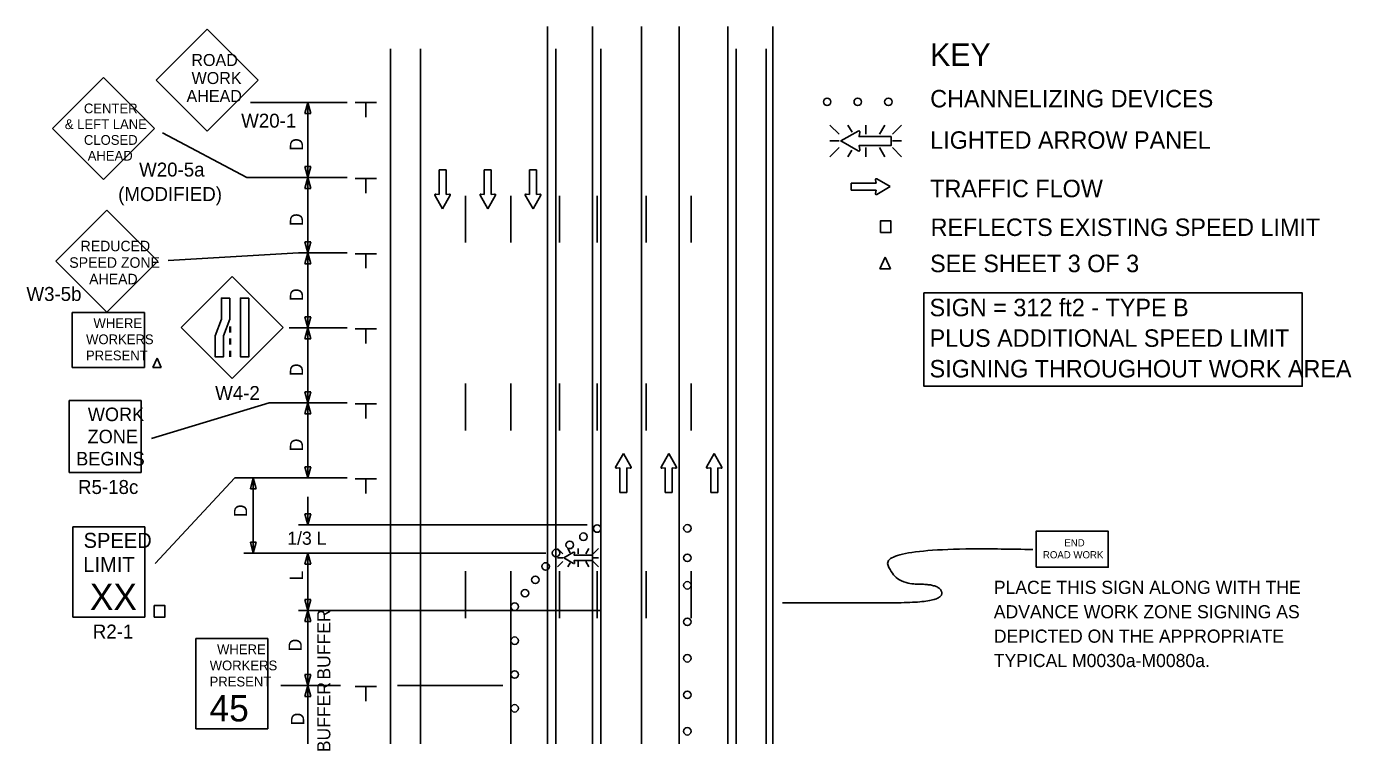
# Model space of a CAD drawing. Extents: x 16724 to 19504, y 5662 to 6979.
# Drawn here: x 16724 to 17429, y 6551 to 6929 of the extents above; entities that cross this region are included whole.
import ezdxf

# ---------------------------------------------------------------- set-up
doc = ezdxf.new("R2010")
doc.units = 0
for name, color, linetype in [('ALI_LEGAL_EX', 7, 'Continuous'), ('MT_SCRATCH_LEVEL_E', 7, 'Continuous'), ('PAVT_EDGE_EX', 7, 'Continuous'), ('TRAFFIC_SIGNS_PR', 7, 'Continuous'), ('TYPICAL_TEXT_DIMEN_EX', 7, 'Continuous'), ('TYPICAL_TEXT_DIMEN_PR', 7, 'Continuous')]:
    doc.layers.add(name, color=color, linetype=linetype)

msp = doc.modelspace()

# ---------------------------------------------------------------- linework, layer by layer
at = {"layer": 'ALI_LEGAL_EX'}
for p, q in [((17001.36, 6131.68), (17001.36, 6928.96)), ((17001.36, 6131.68), (17001.36, 6928.96)), ((17025.36, 6131.68), (17025.36, 6928.96)), ((17025.36, 6131.68), (17025.36, 6928.96)), ((17051.36, 6131.68), (17051.36, 6928.96)), ((17051.36, 6131.68), (17051.36, 6928.96)), ((17071.36, 6131.68), (17071.36, 6928.96)), ((17071.36, 6131.68), (17071.36, 6928.96)), ((17097.36, 6131.68), (17097.36, 6928.96)), ((17097.36, 6131.68), (17097.36, 6928.96)), ((17121.36, 6131.68), (17121.36, 6928.96)), ((17121.36, 6131.68), (17121.36, 6928.96))]:
    msp.add_line(p, q, dxfattribs=at)
for points in [[(16957.81, 6813.81), (16957.81, 6838.81)], [(16981.81, 6813.81), (16981.81, 6838.81)], [(17007.81, 6813.81), (17007.81, 6838.81)], [(17027.81, 6813.81), (17027.81, 6838.81)], [(17053.81, 6813.81), (17053.81, 6838.81)], [(17077.81, 6813.81), (17077.81, 6838.81)], [(16957.81, 6713.81), (16957.81, 6738.81)], [(16981.81, 6713.81), (16981.81, 6738.81)], [(17007.81, 6713.81), (17007.81, 6738.81)], [(17027.81, 6713.81), (17027.81, 6738.81)], [(17053.81, 6713.81), (17053.81, 6738.81)], [(17077.81, 6713.81), (17077.81, 6738.81)], [(16957.81, 6613.81), (16957.81, 6638.81)], [(16981.81, 6613.81), (16981.81, 6638.81)], [(17007.81, 6613.81), (17007.81, 6638.81)], [(17027.81, 6613.81), (17027.81, 6638.81)], [(17053.81, 6613.81), (17053.81, 6638.81)], [(17077.81, 6613.81), (17077.81, 6638.81)]]:
    msp.add_lwpolyline(points, dxfattribs=at)
at = {"layer": 'MT_SCRATCH_LEVEL_E'}
for p, q in [((16947.41, 6852.65), (16943.67, 6852.65)), ((16943.67, 6852.65), (16943.67, 6839.4)), ((16947.41, 6852.65), (16943.67, 6852.65)), ((16943.67, 6852.65), (16943.67, 6839.4)), ((16947.41, 6839.4), (16947.41, 6852.65)), ((16947.41, 6839.4), (16947.41, 6852.65)), ((16971.48, 6852.65), (16967.74, 6852.65)), ((16967.74, 6852.65), (16967.74, 6839.4)), ((16971.48, 6852.65), (16967.74, 6852.65)), ((16967.74, 6852.65), (16967.74, 6839.4)), ((16971.48, 6839.4), (16971.48, 6852.65)), ((16971.48, 6839.4), (16971.48, 6852.65)), ((16995.55, 6852.65), (16991.81, 6852.65)), ((16991.81, 6852.65), (16991.81, 6839.4)), ((16995.55, 6852.65), (16991.81, 6852.65)), ((16991.81, 6852.65), (16991.81, 6839.4)), ((16995.55, 6839.4), (16995.55, 6852.65)), ((16995.55, 6839.4), (16995.55, 6852.65)), ((17175.9, 6847.27), (17176.21, 6845.5)), ((17175.9, 6847.27), (17176.21, 6845.5)), ((17183.82, 6843.64), (17176.58, 6847.75)), ((17183.82, 6843.64), (17176.58, 6847.75)), ((16943.67, 6839.4), (16941.89, 6839.71)), ((16943.67, 6839.4), (16941.89, 6839.71)), ((16949.19, 6839.71), (16947.41, 6839.4)), ((16949.19, 6839.71), (16947.41, 6839.4)), ((16967.74, 6839.4), (16965.96, 6839.71)), ((16967.74, 6839.4), (16965.96, 6839.71)), ((16973.26, 6839.71), (16971.48, 6839.4)), ((16973.26, 6839.71), (16971.48, 6839.4)), ((16991.81, 6839.4), (16990.03, 6839.71)), ((16991.81, 6839.4), (16990.03, 6839.71)), ((16997.33, 6839.71), (16995.55, 6839.4)), ((16997.33, 6839.71), (16995.55, 6839.4)), ((17176.21, 6845.5), (17162.96, 6845.5)), ((17162.96, 6845.5), (17162.96, 6841.75)), ((17176.21, 6845.5), (17162.96, 6845.5)), ((17162.96, 6845.5), (17162.96, 6841.75)), ((17162.96, 6841.75), (17176.21, 6841.75)), ((17162.96, 6841.75), (17176.21, 6841.75)), ((17176.21, 6841.75), (17175.9, 6839.98)), ((17176.21, 6841.75), (17175.9, 6839.98)), ((17176.58, 6839.5), (17183.82, 6843.64)), ((17176.58, 6839.5), (17183.82, 6843.64)), ((16941.41, 6839.03), (16945.56, 6831.79)), ((16941.41, 6839.03), (16945.56, 6831.79)), ((16945.56, 6831.79), (16949.67, 6839.03)), ((16945.56, 6831.79), (16949.67, 6839.03)), ((16965.48, 6839.03), (16969.63, 6831.79)), ((16965.48, 6839.03), (16969.63, 6831.79)), ((16969.63, 6831.79), (16973.74, 6839.03)), ((16969.63, 6831.79), (16973.74, 6839.03)), ((16989.55, 6839.03), (16993.7, 6831.79)), ((16989.55, 6839.03), (16993.7, 6831.79)), ((16993.7, 6831.79), (16997.81, 6839.03)), ((16993.7, 6831.79), (16997.81, 6839.03)), ((17041.75, 6701.53), (17037.64, 6694.29)), ((17041.75, 6701.53), (17037.64, 6694.29)), ((17045.89, 6694.29), (17041.75, 6701.53)), ((17045.89, 6694.29), (17041.75, 6701.53)), ((17065.92, 6701.53), (17061.81, 6694.29)), ((17065.92, 6701.53), (17061.81, 6694.29)), ((17070.06, 6694.29), (17065.92, 6701.53)), ((17070.06, 6694.29), (17065.92, 6701.53)), ((17090.09, 6701.53), (17085.97, 6694.29)), ((17090.09, 6701.53), (17085.97, 6694.29)), ((17094.23, 6694.29), (17090.09, 6701.53)), ((17094.23, 6694.29), (17090.09, 6701.53)), ((17038.12, 6693.61), (17039.89, 6693.92)), ((17038.12, 6693.61), (17039.89, 6693.92)), ((17039.89, 6693.92), (17039.89, 6680.67)), ((17039.89, 6693.92), (17039.89, 6680.67)), ((17043.64, 6680.67), (17043.64, 6693.92)), ((17043.64, 6693.92), (17045.41, 6693.61)), ((17043.64, 6680.67), (17043.64, 6693.92)), ((17043.64, 6693.92), (17045.41, 6693.61)), ((17062.29, 6693.61), (17064.06, 6693.92)), ((17062.29, 6693.61), (17064.06, 6693.92)), ((17064.06, 6693.92), (17064.06, 6680.67)), ((17064.06, 6693.92), (17064.06, 6680.67)), ((17067.81, 6680.67), (17067.81, 6693.92)), ((17067.81, 6693.92), (17069.58, 6693.61)), ((17067.81, 6680.67), (17067.81, 6693.92)), ((17067.81, 6693.92), (17069.58, 6693.61)), ((17086.46, 6693.61), (17088.23, 6693.92)), ((17086.46, 6693.61), (17088.23, 6693.92)), ((17088.23, 6693.92), (17088.23, 6680.67)), ((17088.23, 6693.92), (17088.23, 6680.67)), ((17091.98, 6680.67), (17091.98, 6693.92)), ((17091.98, 6693.92), (17093.75, 6693.61)), ((17091.98, 6680.67), (17091.98, 6693.92)), ((17091.98, 6693.92), (17093.75, 6693.61)), ((17039.89, 6680.67), (17043.64, 6680.67)), ((17039.89, 6680.67), (17043.64, 6680.67)), ((17064.06, 6680.67), (17067.81, 6680.67)), ((17064.06, 6680.67), (17067.81, 6680.67)), ((17088.23, 6680.67), (17091.98, 6680.67)), ((17088.23, 6680.67), (17091.98, 6680.67))]:
    msp.add_line(p, q, dxfattribs=at)
for centre, start, end in [((17176.36, 6847.35), 60.42484, 189.96381), ((17176.36, 6847.35), 60.42484, 189.96381), ((16941.82, 6839.25), 80.03619, 209.77312), ((16941.82, 6839.25), 80.03619, 209.77312), ((16949.26, 6839.25), 330.42484, 99.96381), ((16949.26, 6839.25), 330.42484, 99.96381), ((16965.89, 6839.25), 80.03619, 209.77312), ((16965.89, 6839.25), 80.03619, 209.77312), ((16973.33, 6839.25), 330.42484, 99.96381), ((16973.33, 6839.25), 330.42484, 99.96381), ((16989.96, 6839.25), 80.03619, 209.77312), ((16989.96, 6839.25), 80.03619, 209.77312), ((16997.4, 6839.25), 330.42484, 99.96381), ((16997.4, 6839.25), 330.42484, 99.96381), ((17176.36, 6839.91), 170.03619, 299.77312), ((17176.36, 6839.91), 170.03619, 299.77312), ((17038.04, 6694.07), 150.42484, 279.96381), ((17038.04, 6694.07), 150.42484, 279.96381), ((17045.48, 6694.07), 260.03619, 29.77312), ((17045.48, 6694.07), 260.03619, 29.77312), ((17062.21, 6694.07), 150.42484, 279.96381), ((17062.21, 6694.07), 150.42484, 279.96381), ((17069.65, 6694.07), 260.03619, 29.77312), ((17069.65, 6694.07), 260.03619, 29.77312), ((17086.38, 6694.07), 150.42484, 279.96381), ((17086.38, 6694.07), 150.42484, 279.96381), ((17093.82, 6694.07), 260.03619, 29.77312), ((17093.82, 6694.07), 260.03619, 29.77312)]:
    msp.add_arc(centre, 0.463, start, end, dxfattribs=at)
at = {"layer": 'PAVT_EDGE_EX'}
for p, q in [((16917.81, 6917), (16917.81, 6089.02)), ((16933.81, 6917), (16933.81, 6089.02)), ((17005.81, 6917), (17005.81, 6089.02)), ((17029.81, 6917), (17029.81, 6089.02)), ((17101.81, 6917), (17101.81, 6089.02)), ((17117.81, 6917), (17117.81, 6089.02))]:
    msp.add_line(p, q, dxfattribs=at)
msp.add_lwpolyline([(17029.81, 6617.94), (16981.81, 6617.94), (16981.81, 6537.94), (17029.81, 6537.94)], close=True, dxfattribs=at)
at = {"layer": 'TRAFFIC_SIGNS_PR'}
for p, q in [((16820.31, 6927.52), (16793.16, 6900.36)), ((16847.46, 6900.36), (16820.31, 6927.52)), ((16765.09, 6901.75), (16737.93, 6874.6)), ((16792.24, 6874.6), (16765.09, 6901.75)), ((16793.16, 6900.36), (16820.31, 6873.21)), ((16820.31, 6873.21), (16847.46, 6900.36)), ((17151.69, 6876.45), (17156.62, 6871.52)), ((17163.45, 6872.63), (17161.24, 6876.45)), ((17170.77, 6871.52), (17170.77, 6876.45)), ((17178, 6871.52), (17180.85, 6876.45)), ((17184.92, 6871.52), (17189.85, 6876.45)), ((16737.93, 6874.6), (16765.09, 6847.45)), ((16765.09, 6847.45), (16792.24, 6874.6)), ((17156.62, 6867.96), (17151.69, 6867.96)), ((17184.92, 6867.96), (17189.85, 6867.96)), ((17151.69, 6859.47), (17156.62, 6864.41)), ((17161.2, 6859.47), (17163.31, 6863.13)), ((17170.77, 6864.41), (17170.77, 6859.47)), ((17180.9, 6859.47), (17178.05, 6864.41)), ((17184.92, 6864.41), (17189.85, 6859.47)), ((16766.85, 6831.07), (16739.69, 6803.91)), ((16794, 6803.91), (16766.85, 6831.07)), ((16739.69, 6803.91), (16766.85, 6776.76)), ((16766.85, 6776.76), (16794, 6803.91)), ((16833.56, 6795.73), (16806.4, 6768.58)), ((16860.71, 6768.58), (16833.56, 6795.73)), ((16748.45, 6776.64), (16786.85, 6776.64)), ((16748.45, 6747.32), (16748.45, 6776.64)), ((16786.85, 6747.32), (16786.85, 6776.64)), ((16806.4, 6768.58), (16833.56, 6741.43)), ((16832.31, 6769.07), (16832.31, 6765.87)), ((16832.31, 6762.67), (16832.31, 6759.47)), ((16832.71, 6769.07), (16832.71, 6765.87)), ((16832.71, 6762.67), (16832.71, 6759.47)), ((16833.56, 6741.43), (16860.71, 6768.58)), ((16832.31, 6756.27), (16832.31, 6753.07)), ((16832.71, 6756.27), (16832.71, 6753.07)), ((16748.45, 6747.32), (16786.85, 6747.32)), ((16746.75, 6691.37), (16746.75, 6729.77)), ((16746.75, 6729.77), (16785.15, 6729.77)), ((16785.15, 6691.37), (16785.15, 6729.77)), ((16746.75, 6691.37), (16785.15, 6691.37)), ((16748.74, 6662.36), (16787.14, 6662.36)), ((16748.74, 6614.36), (16748.74, 6662.36)), ((16787.14, 6614.36), (16787.14, 6662.36)), ((17006.73, 6650.82), (17009.55, 6648)), ((17013.45, 6648.63), (17012.19, 6650.82)), ((17017.63, 6648), (17017.63, 6650.82)), ((17021.76, 6648), (17023.39, 6650.82)), ((17025.72, 6648), (17028.54, 6650.82)), ((17009.55, 6645.97), (17006.73, 6645.97)), ((17006.73, 6641.12), (17009.55, 6643.94)), ((17012.16, 6641.11), (17013.37, 6643.21)), ((17017.63, 6643.94), (17017.63, 6641.11)), ((17023.42, 6641.11), (17021.79, 6643.94)), ((17025.72, 6645.97), (17028.54, 6645.97)), ((17025.72, 6643.94), (17028.54, 6641.11)), ((16748.74, 6614.36), (16787.14, 6614.36)), ((16814.23, 6602.91), (16852.63, 6602.91)), ((16814.23, 6554.91), (16814.23, 6602.91)), ((16852.63, 6554.91), (16852.63, 6602.91)), ((16814.23, 6554.91), (16852.63, 6554.91))]:
    msp.add_line(p, q, dxfattribs=at)
for points in [[(17166.7, 6873.24), (17157.41, 6867.96), (17166.7, 6862.64)], [(17167.57, 6863.27), (17167.17, 6865.54), (17184.18, 6865.54), (17184.18, 6870.34), (17167.17, 6870.34), (17167.57, 6872.62)], [(17181.07, 6806.1), (17178.28, 6799.93)], [(17178.28, 6799.93), (17181.07, 6806.1)], [(17183.87, 6799.93), (17181.07, 6806.1)], [(17181.07, 6806.1), (17183.87, 6799.93)], [(17178.28, 6799.93), (17183.87, 6799.93)], [(17183.87, 6799.93), (17178.28, 6799.93)], [(16793.6, 6752.26), (16791.37, 6747.32)], [(16791.37, 6747.32), (16793.6, 6752.26)], [(16795.84, 6747.32), (16793.6, 6752.26)], [(16793.6, 6752.26), (16795.84, 6747.32)], [(16791.37, 6747.32), (16795.84, 6747.32)], [(16795.84, 6747.32), (16791.37, 6747.32)], [(17015.3, 6648.98), (17009.99, 6645.97), (17015.3, 6642.93)], [(17015.8, 6643.28), (17015.57, 6644.58), (17025.3, 6644.58), (17025.3, 6647.32), (17015.57, 6647.32), (17015.81, 6648.63)]]:
    msp.add_lwpolyline(points, dxfattribs=at)
for points in [[(17178.57, 6819.2), (17184.16, 6819.2), (17184.16, 6825.37), (17178.57, 6825.37)], [(16832.31, 6784.31), (16832.31, 6773.13), (16828.97, 6764.25), (16828.97, 6753.07), (16824.47, 6753.07), (16824.47, 6764.25), (16827.82, 6773.13), (16827.82, 6784.31)], [(16842.45, 6784.31), (16842.45, 6753.07), (16837.95, 6753.07), (16837.95, 6784.31)], [(17261.42, 6640.9), (17299.82, 6640.9), (17299.82, 6660.1), (17261.42, 6660.1)], [(16792.15, 6614.36), (16797.75, 6614.36), (16797.75, 6620.53), (16792.15, 6620.53)]]:
    msp.add_lwpolyline(points, close=True, dxfattribs=at)
for centre in [(17150.2, 6888.8), (17166.5, 6888.8), (17182.8, 6888.8), (17027.8, 6661.52), (17075.83, 6661.64), (17020.5, 6657.17), (17005.9, 6648.47), (17013.2, 6652.82), (17000.4, 6641.34), (17075.79, 6645.93), (16994.9, 6634.21), (16989.41, 6627.09), (17075.79, 6631.28), (16983.91, 6619.95), (17075.79, 6611.84), (16983.91, 6601.76), (17075.79, 6592.4), (16983.91, 6583.76), (17075.79, 6572.96), (16983.91, 6565.76), (17075.79, 6553.52)]:
    msp.add_circle(centre, 2, dxfattribs=at)
for centre, radius, start, end in [((17166.98, 6872.71), 0.598, 350.73078, 118.89165), ((17166.98, 6863.17), 0.597, 241.48329, 9.95933), ((17015.47, 6648.68), 0.341, 350.73078, 118.89165), ((17015.47, 6643.23), 0.341, 241.48329, 9.95933)]:
    msp.add_arc(centre, radius, start, end, dxfattribs=at)
at = {"layer": 'TYPICAL_TEXT_DIMEN_EX'}
msp.add_lwpolyline([(17201.7, 6787.03), (17403.05, 6787.03), (17403.05, 6737.36), (17201.7, 6737.36)], close=True, dxfattribs=at)
at = {"layer": 'TYPICAL_TEXT_DIMEN_PR'}
for p, q in [((16843.26, 6888.47), (16894.81, 6888.47)), ((16872.24, 6882.6), (16873.81, 6888.47)), ((16873.81, 6882.6), (16872.24, 6882.6)), ((16873.81, 6888.47), (16875.38, 6882.6)), ((16873.81, 6888.47), (16873.81, 6848.47)), ((16875.38, 6882.6), (16873.81, 6882.6)), ((16899.06, 6888.47), (16910.31, 6888.47)), ((16904.69, 6888.47), (16904.69, 6880.68)), ((16796.57, 6872.3), (16841.3, 6848.47)), ((16873.81, 6848.47), (16872.24, 6854.33)), ((16872.24, 6854.33), (16873.81, 6854.33)), ((16873.81, 6854.33), (16875.38, 6854.33)), ((16875.38, 6854.33), (16873.81, 6848.47)), ((16841.3, 6848.47), (16894.81, 6848.47)), ((16872.24, 6842.6), (16873.81, 6848.47)), ((16873.81, 6848.47), (16875.38, 6842.6)), ((16873.81, 6848.47), (16873.81, 6808.47)), ((16899.06, 6847.94), (16910.31, 6847.94)), ((16904.69, 6847.94), (16904.69, 6840.15)), ((16873.81, 6842.6), (16872.24, 6842.6)), ((16875.38, 6842.6), (16873.81, 6842.6)), ((16873.81, 6808.47), (16872.24, 6814.33)), ((16872.24, 6814.33), (16873.81, 6814.33)), ((16873.81, 6814.33), (16875.38, 6814.33)), ((16875.38, 6814.33), (16873.81, 6808.47)), ((16868.81, 6808.47), (16799.51, 6804.25)), ((16868.81, 6808.47), (16894.81, 6808.47)), ((16872.24, 6802.6), (16873.81, 6808.47)), ((16873.81, 6808.47), (16875.38, 6802.6)), ((16873.81, 6808.47), (16873.81, 6768.47)), ((16899.06, 6807.94), (16910.31, 6807.94)), ((16904.69, 6807.94), (16904.69, 6800.15)), ((16873.81, 6802.6), (16872.24, 6802.6)), ((16875.38, 6802.6), (16873.81, 6802.6)), ((16873.81, 6768.47), (16872.24, 6774.33)), ((16872.24, 6774.33), (16873.81, 6774.33)), ((16873.81, 6774.33), (16875.38, 6774.33)), ((16875.38, 6774.33), (16873.81, 6768.47)), ((16863.88, 6768.47), (16894.81, 6768.47)), ((16872.24, 6762.6), (16873.81, 6768.47)), ((16873.81, 6762.6), (16872.24, 6762.6)), ((16873.81, 6768.47), (16875.38, 6762.6)), ((16873.81, 6768.47), (16873.81, 6728.47)), ((16875.38, 6762.6), (16873.81, 6762.6)), ((16899.06, 6767.94), (16910.31, 6767.94)), ((16904.69, 6767.94), (16904.69, 6760.15)), ((16873.81, 6728.47), (16872.24, 6734.33)), ((16872.24, 6734.33), (16873.81, 6734.33)), ((16873.81, 6734.33), (16875.38, 6734.33)), ((16875.38, 6734.33), (16873.81, 6728.47)), ((16853.18, 6728.47), (16790.66, 6709.54)), ((16853.18, 6728.47), (16894.81, 6728.47)), ((16872.24, 6722.6), (16873.81, 6728.47)), ((16873.81, 6728.47), (16875.38, 6722.6)), ((16873.81, 6728.47), (16873.81, 6688.47)), ((16899.06, 6727.94), (16910.31, 6727.94)), ((16904.69, 6727.94), (16904.69, 6720.15)), ((16873.81, 6722.6), (16872.24, 6722.6)), ((16875.38, 6722.6), (16873.81, 6722.6)), ((16873.81, 6688.47), (16872.24, 6694.33)), ((16872.24, 6694.33), (16873.81, 6694.33)), ((16873.81, 6694.33), (16875.38, 6694.33)), ((16875.38, 6694.33), (16873.81, 6688.47)), ((16834.91, 6688.47), (16792.53, 6642.95)), ((16834.91, 6688.47), (16873.81, 6688.47)), ((16843.25, 6682.6), (16844.82, 6688.47)), ((16844.82, 6688.47), (16844.82, 6648.47)), ((16844.82, 6688.47), (16846.39, 6682.6)), ((16868.81, 6688.47), (16894.81, 6688.47)), ((16899.06, 6687.94), (16910.31, 6687.94)), ((16904.69, 6687.94), (16904.69, 6680.15)), ((16844.82, 6682.6), (16843.25, 6682.6)), ((16846.39, 6682.6), (16844.82, 6682.6)), ((16873.81, 6663.53), (16873.81, 6678.46)), ((16868.81, 6663.53), (17022.42, 6663.53)), ((16873.81, 6663.53), (16872.24, 6669.4)), ((16872.24, 6669.4), (16873.81, 6669.4)), ((16873.81, 6669.4), (16875.38, 6669.4)), ((16875.38, 6669.4), (16873.81, 6663.53)), ((16844.82, 6648.47), (16843.25, 6654.33)), ((16843.25, 6654.33), (16844.82, 6654.33)), ((16844.82, 6654.33), (16846.39, 6654.33)), ((16846.39, 6654.33), (16844.82, 6648.47)), ((16839.82, 6648.47), (17000.57, 6648.47)), ((16872.24, 6642.6), (16873.81, 6648.47)), ((16873.81, 6642.6), (16872.24, 6642.6)), ((16873.81, 6648.47), (16875.38, 6642.6)), ((16873.81, 6648.47), (16873.81, 6617.94)), ((16875.38, 6642.6), (16873.81, 6642.6)), ((16873.81, 6617.94), (16872.24, 6623.8)), ((16872.24, 6623.8), (16873.81, 6623.8)), ((16873.81, 6623.8), (16875.38, 6623.8)), ((16875.38, 6623.8), (16873.81, 6617.94)), ((16868.81, 6617.94), (17029.81, 6617.94)), ((16872.24, 6612.08), (16873.81, 6617.94)), ((16873.81, 6617.94), (16873.81, 6577.94)), ((16873.81, 6617.94), (16875.38, 6612.08)), ((16873.81, 6612.08), (16872.24, 6612.08)), ((16875.38, 6612.08), (16873.81, 6612.08)), ((16873.81, 6577.94), (16872.24, 6583.8)), ((16872.24, 6583.8), (16873.81, 6583.8)), ((16873.81, 6583.8), (16875.38, 6583.8)), ((16875.38, 6583.8), (16873.81, 6577.94)), ((16859.39, 6577.94), (16891.23, 6577.94)), ((16872.24, 6572.08), (16873.81, 6577.94)), ((16873.81, 6572.08), (16872.24, 6572.08)), ((16873.81, 6577.94), (16873.81, 6537.94)), ((16873.81, 6577.94), (16875.38, 6572.08)), ((16875.38, 6572.08), (16873.81, 6572.08)), ((16899.06, 6577.41), (16910.31, 6577.41)), ((16904.69, 6577.41), (16904.69, 6569.63)), ((16921.53, 6577.94), (16977.55, 6577.94))]:
    msp.add_line(p, q, dxfattribs=at)
msp.add_open_spline([(17259.69, 6650.35), (17179.04, 6652.51), (17186.04, 6631.92), (17211.21, 6631.92), (17211.21, 6622.01), (17161.57, 6622.01), (17126.5, 6622.01)], degree=2, dxfattribs=at)

# ---------------------------------------------------------------- texts
at = {"layer": 'TRAFFIC_SIGNS_PR'}
for s, height, p in [('ROAD', 6.4, (16811.85, 6907.9)), ('WORK', 6.4, (16811.96, 6898.3)), ('AHEAD', 6.4, (16809.27, 6888.7)), ('CENTER', 5.2, (16754.66, 6882.71)), ('W20-1', 7.44, (16838.37, 6875.06)), ('& LEFT LANE', 5.2, (16744.53, 6874.31)), ('CLOSED', 5.2, (16754.67, 6865.91)), ('AHEAD', 5.2, (16756.69, 6857.51)), ('W20-5a', 7.44, (16784.04, 6849.02)), ('(MODIFIED)', 7.44, (16772.9, 6835.98)), ('REDUCED', 5.6, (16752.9, 6809.22)), ('SPEED ZONE', 5.6, (16746.9, 6800.42)), ('W3-5b', 7.44, (16724.08, 6782.76)), ('AHEAD', 5.6, (16757.46, 6791.62)), ('WHERE', 5.2, (16759.76, 6768.32)), ('WORKERS', 5.2, (16755.84, 6759.72)), ('PRESENT', 5.2, (16755.77, 6751.12)), ('W4-2', 7.44, (16824.51, 6729.99)), ('WORK', 7.217, (16756.75, 6718.74)), ('ZONE', 7.217, (16756.63, 6706.93)), ('BEGINS', 7.217, (16750.56, 6695.12)), ('R5-18c', 7.44, (16751.56, 6679.93)), ('SPEED', 8, (16754.5, 6651.23)), ('ROAD WORK', 3.831, (17265.03, 6645.65)), ('END', 3.831, (17276.43, 6652.03)), ('LIMIT', 8, (16754.34, 6638.43)), ('XX', 14.031, (16757.85, 6618.12)), ('PLACE THIS SIGN ALONG WITH THE', 7, (17238.88, 6626.71)), ('ADVANCE WORK ZONE SIGNING AS', 7, (17238.88, 6613.71)), ('R2-1', 7.44, (16759.41, 6602.92)), ('DEPICTED ON THE APPROPRIATE', 7, (17238.88, 6600.71)), ('WHERE', 5.2, (16825.54, 6594.6)), ('TYPICAL M0030a-M0080a.', 7, (17238.88, 6587.71)), ('WORKERS', 5.2, (16821.62, 6586)), ('PRESENT', 5.2, (16821.55, 6577.4)), ('45', 14.031, (16821.54, 6558.77))]:
    msp.add_text(s, height=height, dxfattribs=at).set_placement(p)
at = {"layer": 'TYPICAL_TEXT_DIMEN_EX'}
for s, height, p in [('KEY', 12, (17205.04, 6907.91)), ('CHANNELIZING DEVICES', 9.3, (17205.04, 6885.86)), ('LIGHTED ARROW PANEL', 9.3, (17205.04, 6863.81)), ('TRAFFIC FLOW', 9.3, (17205.04, 6838.01)), ('REFLECTS EXISTING SPEED LIMIT', 9.3, (17205.26, 6817.37)), ('SEE SHEET 3 OF 3', 9.3, (17204.97, 6798.09)), ('SIGN = 312 ft2 - TYPE B', 9.3, (17204.71, 6774.62)), ('PLUS ADDITIONAL SPEED LIMIT', 9.3, (17204.71, 6758.32)), ('SIGNING THROUGHOUT WORK AREA', 9.3, (17204.71, 6742.02))]:
    msp.add_text(s, height=height, dxfattribs=at).set_placement(p)
at = {"layer": 'TYPICAL_TEXT_DIMEN_PR'}
for s, p in [('D', (16871.25, 6862.68)), ('D', (16871.25, 6822.68)), ('D', (16871.25, 6782.68)), ('D', (16871.25, 6742.68)), ('D', (16871.25, 6702.68)), ('D', (16841.53, 6667.58)), ('L', (16871.25, 6633.85)), ('BUFFER', (16885.84, 6581.06)), ('D', (16870.62, 6596.06)), ('BUFFER', (16885.84, 6542.37)), ('D', (16871.89, 6556.69))]:
    msp.add_text(s, height=7, rotation=90, dxfattribs=at).set_placement(p)
msp.add_text('1/3 L', height=7, dxfattribs=at).set_placement((16862.91, 6652.87))

doc.saveas('drawing.dxf')
